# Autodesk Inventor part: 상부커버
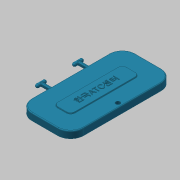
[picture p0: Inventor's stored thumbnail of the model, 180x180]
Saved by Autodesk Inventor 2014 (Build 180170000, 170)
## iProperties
Created: 2016-02
Part Number: 상부커버
Material: ABS 플라스틱
Document SubType Name: Modeling
Designer: mduedu
Density: 2.71 g/cm^3
Mass: 42.0587 g
Surface Area: 149.263 cm^2
Volume: 15.5198 cm^3
Appearance: Turquoise
Author: mduedu
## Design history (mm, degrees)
sketch "스케치1"
  geometry: L1 (30, 60)-(-30, 60); L2 (-30, 60)-(-30, -60); L3 (-30, -60)-(30, -60); L4 (30, -60)-(30, 60); L5 (30, 60)-(-30, -60); L6 (-30, 60)-(30, -60); 1 further point
  constraints: 12 end point, 2 midpoint, 2 parallel, 1 horizontal, 1 perpendicular
  dimensions: "d0" = 60 distance of L2.end L3.end; "d2" = 120 distance of L1.end L2.end
extrude "돌출1" new body sketch "스케치1" distance "d3" = 8; taper "d4" = 0 deg
fillet "모깎기1" dims "d5" = 15
node "작업 평면1"
sketch "스케치7"
  geometry: L1 (-39, 4)-(129, 4) reference; L2 (65, 2)-(68, 2); L3 (68, 2)-(68, 6); L4 (68, 6)-(65, 6); L5 (65, 6)-(65, 2); L6 (65, 2)-(68, 6); L7 (68, 2)-(65, 6); 2 further points
  constraints: 12 end point, 2 midpoint, 2 parallel, 1 horizontal, 1 perpendicular, 1 point on line
  dimensions: "d33" = 4 distance of L2.end L3.end; "d35" = 3 distance of L3.end L4.end; "d36" = 20 distance from line of L5 point (45, 0)
extrude "돌출3" join sketch "스케치7" distance "d37" = 15; taper "d38" = 0 deg
fillet "모깎기6" dims "d39" = 2
node "작업 평면3"
sketch "스케치8"
  geometry: A1 r 2 centre (-13, 2) between (-13, 4) and (-13, 0) reference; 2 further points
  constraints: 1 coincident, 1 vertical alignment, 2 other
extrude "돌출4" join sketch "스케치8" stored distance "d40" = 12; taper "d41" = 0 deg
fillet "모깎기7" dims "d42" = 2
fillet "모깎기8" dims "d43" = 1
fillet "모깎기9" dims "d44" = 1
sketch "스케치2"
  geometry: L1 (30, 45)-(30, -45) reference; L2 (15, -60)-(-15, -60) reference; L3 (-30, -45)-(-30, 45) reference; L4 (-15, 60)-(15, 60) reference; L5 (25, 45)-(25, -45); L6 (15, -55)-(-15, -55); L7 (-25, -45)-(-25, 45); L8 (-15, 55)-(15, 55); A1 r 15 centre (15, 45) between (30, 45) and (15, 60) reference; A2 r 15 centre (15, -45) between (15, -60) and (30, -45) reference; A3 r 15 centre (-15, -45) between (-30, -45) and (-15, -60) reference; A4 r 15 centre (-15, 45) between (-15, 60) and (-30, 45) reference; A5 r 10 centre (15, 45) between (25, 45) and (15, 55); A6 r 10 centre (15, -45) between (15, -55) and (25, -45); A7 r 10 centre (-15, -45) between (-25, -45) and (-15, -55); A8 r 10 centre (-15, 45) between (-15, 55) and (-25, 45); 4 further points
  constraints: 8 end point, 8 point on circle, 4 centre point, 4 midpoint, 7 other
  dimensions: "d8" = 5 distance between parallel lines of L7 L3
hole "구멍1" sketch "스케치2" at (25, 0) diameter "d9" = 5; stored, may be unused: countersink angle "d13" = 90 deg, drill point angle "d15" = 118 deg; dims "d10" = 6, "d11" = 4, "d12" = 2, "d14" = 8
sketch "스케치3"
  geometry: L1 (10, -40)-(-10, -40); L2 (-10, -40)-(-10, 40); L3 (-10, 40)-(10, 40); L4 (10, 40)-(10, -40); L5 (10, -40)-(-10, 40); L6 (-10, -40)-(10, 40); 1 further point
  constraints: 12 end point, 2 midpoint, 2 parallel, 1 horizontal, 1 perpendicular
  dimensions: "d16" = 80 distance of L1.end L2.end; "d18" = 20 distance of L2.end L3.end
extrude "돌출2" join sketch "스케치3" distance "d19" = 1; taper "d20" = 0 deg
fillet "모깎기2" dims "d21" = 5
fillet "모깎기3" dims "d22" = 0.3
sketch "스케치4"
  geometry: 2 further points
  constraints: 1 coincident, 1 other
feature "엠보싱1" sketch "스케치4" dims "d8" = 5, "d24" = 0.5, "d25" = 0
fillet "모깎기10" dims "d45" = 1
node "솔리드1"
mirror "대칭1"
node "절단 모서리 투영1"
